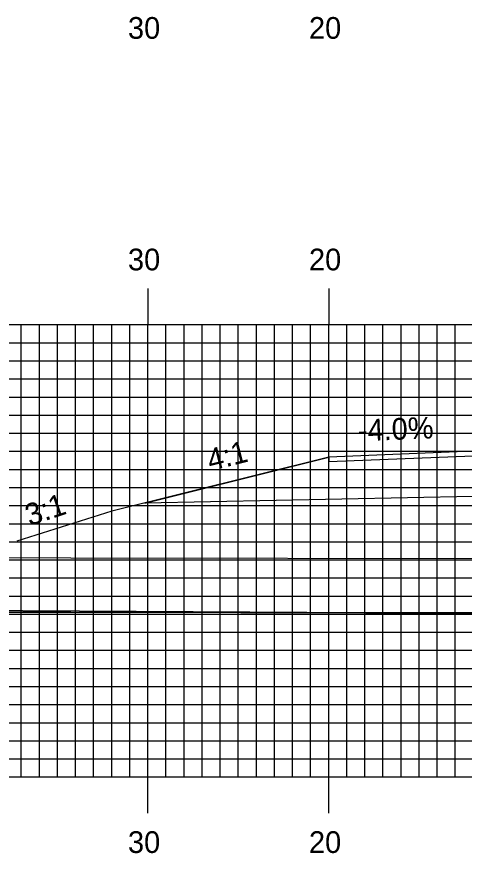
# Model space of a CAD drawing. Extents: x 1804290 to 1804634, y 442591 to 442811.
# Drawn here: x 1804418.91 to 1804443.67, y 442649.45 to 442695.68 of the extents above; entities that cross this region are included whole.
import ezdxf

# ---------------------------------------------------------------- set-up
doc = ezdxf.new("R2010")
doc.units = 0
for name, color, linetype in [('ANNOTATION', 7, 'Continuous'), ('D_Drainage_Culvert', 7, 'Continuous'), ('D_Roadway_Edge_Shoulder', 7, 'Continuous'), ('D_Roadway_SlopeLines', 7, 'Continuous'), ('D_Roadway_SubGrade', 7, 'Continuous'), ('H_V ANNOTATION', 7, 'Continuous'), ('MAJOR', 7, 'Continuous'), ('MINOR', 7, 'Continuous'), ('S_Roadway_Centerline', 7, 'Continuous')]:
    doc.layers.add(name, color=color, linetype=linetype)

msp = doc.modelspace()

# ---------------------------------------------------------------- linework, layer by layer
at = {"layer": 'D_Drainage_Culvert'}
msp.add_line((1804407.504, 442662.794), (1804505.89, 442662.656), dxfattribs=at)
msp.add_lwpolyline([(1804409.888, 442662.791), (1804409.893, 442665.791), (1804505.893, 442665.645), (1804505.888, 442662.645)], close=True, dxfattribs=at)
at = {"layer": 'D_Roadway_Edge_Shoulder'}
msp.add_lwpolyline([(1804444.167, 442671.668), (1804436.167, 442671.348), (1804436.167, 442671.098), (1804444.167, 442671.418)], close=True, dxfattribs=at)
at = {"layer": 'D_Roadway_SlopeLines'}
msp.add_lwpolyline([(1804436.167, 442671.348), (1804424.167, 442668.348), (1804418.912, 442666.699)], dxfattribs=at)
at = {"layer": 'D_Roadway_SubGrade'}
msp.add_lwpolyline([(1804444.167, 442669.168), (1804425.993, 442668.805), (1804436.167, 442671.348), (1804436.167, 442671.098), (1804444.167, 442671.418), (1804456.167, 442671.706), (1804468.167, 442671.994), (1804476.167, 442671.674), (1804476.167, 442671.924), (1804486.341, 442669.381), (1804468.167, 442669.744), (1804456.167, 442669.456)], close=True, dxfattribs=at)
at = {"layer": 'MAJOR'}
for p, q in [((1804426.167, 442680.669), (1804426.167, 442678.665)), ((1804436.167, 442680.669), (1804436.167, 442678.665)), ((1804316.167, 442678.665), (1804596.167, 442678.665)), ((1804316.167, 442678.665), (1804596.167, 442678.665)), ((1804426.167, 442653.665), (1804426.167, 442678.665)), ((1804436.167, 442653.665), (1804436.167, 442678.665)), ((1804316.167, 442673.665), (1804596.167, 442673.665)), ((1804316.167, 442668.665), (1804596.167, 442668.665)), ((1804316.167, 442663.665), (1804596.167, 442663.665)), ((1804316.167, 442658.665), (1804596.167, 442658.665)), ((1804316.167, 442653.665), (1804596.167, 442653.665)), ((1804316.167, 442653.665), (1804596.167, 442653.665)), ((1804426.167, 442651.661), (1804426.167, 442653.665)), ((1804436.167, 442651.661), (1804436.167, 442653.665))]:
    msp.add_line(p, q, dxfattribs=at)
at = {"layer": 'MINOR'}
for p, q in [((1804419.167, 442653.665), (1804419.167, 442678.665)), ((1804420.167, 442653.665), (1804420.167, 442678.665)), ((1804421.167, 442653.665), (1804421.167, 442678.665)), ((1804422.167, 442653.665), (1804422.167, 442678.665)), ((1804423.167, 442653.665), (1804423.167, 442678.665)), ((1804424.167, 442653.665), (1804424.167, 442678.665)), ((1804425.167, 442653.665), (1804425.167, 442678.665)), ((1804427.167, 442653.665), (1804427.167, 442678.665)), ((1804428.167, 442653.665), (1804428.167, 442678.665)), ((1804429.167, 442653.665), (1804429.167, 442678.665)), ((1804430.167, 442653.665), (1804430.167, 442678.665)), ((1804431.167, 442653.665), (1804431.167, 442678.665)), ((1804432.167, 442653.665), (1804432.167, 442678.665)), ((1804433.167, 442653.665), (1804433.167, 442678.665)), ((1804434.167, 442653.665), (1804434.167, 442678.665)), ((1804435.167, 442653.665), (1804435.167, 442678.665)), ((1804437.167, 442653.665), (1804437.167, 442678.665)), ((1804438.167, 442653.665), (1804438.167, 442678.665)), ((1804439.167, 442653.665), (1804439.167, 442678.665)), ((1804440.167, 442653.665), (1804440.167, 442678.665)), ((1804441.167, 442653.665), (1804441.167, 442678.665)), ((1804442.167, 442653.665), (1804442.167, 442678.665)), ((1804443.167, 442653.665), (1804443.167, 442678.665)), ((1804316.167, 442677.665), (1804596.167, 442677.665)), ((1804316.167, 442676.665), (1804596.167, 442676.665)), ((1804316.167, 442675.665), (1804596.167, 442675.665)), ((1804316.167, 442674.665), (1804596.167, 442674.665)), ((1804316.167, 442672.665), (1804596.167, 442672.665)), ((1804316.167, 442671.665), (1804596.167, 442671.665)), ((1804316.167, 442670.665), (1804596.167, 442670.665)), ((1804316.167, 442669.665), (1804596.167, 442669.665)), ((1804316.167, 442667.665), (1804596.167, 442667.665)), ((1804316.167, 442666.665), (1804596.167, 442666.665)), ((1804316.167, 442665.665), (1804596.167, 442665.665)), ((1804316.167, 442664.665), (1804596.167, 442664.665)), ((1804316.167, 442662.665), (1804596.167, 442662.665)), ((1804316.167, 442661.665), (1804596.167, 442661.665)), ((1804316.167, 442660.665), (1804596.167, 442660.665)), ((1804316.167, 442659.665), (1804596.167, 442659.665)), ((1804316.167, 442657.665), (1804596.167, 442657.665)), ((1804316.167, 442656.665), (1804596.167, 442656.665)), ((1804316.167, 442655.665), (1804596.167, 442655.665)), ((1804316.167, 442654.665), (1804596.167, 442654.665))]:
    msp.add_line(p, q, dxfattribs=at)
at = {"layer": 'S_Roadway_Centerline'}
msp.add_lwpolyline([(1804392.455, 442662.786), (1804403.753, 442662.746), (1804414.339, 442662.882), (1804416.075, 442662.891), (1804434.951, 442662.77), (1804441.486, 442662.699), (1804450.248, 442662.785), (1804459.333, 442662.638), (1804461.991, 442662.67), (1804464.615, 442662.608), (1804482.103, 442662.436), (1804485.564, 442662.421), (1804488.839, 442662.416), (1804494.685, 442662.541), (1804511.409, 442662.696), (1804519.927, 442662.797)], dxfattribs=at)

# ---------------------------------------------------------------- texts
at = {"layer": 'ANNOTATION'}
for s, rotation, p in [('-4.0%', 2.2906, (1804437.799, 442672.215)), ('4:1', 14.0362, (1804429.616, 442670.572)), ('3:1', 18.4348, (1804419.624, 442667.523))]:
    msp.add_text(s, height=1.2, rotation=rotation, dxfattribs=at).set_placement(p)
at = {"layer": 'H_V ANNOTATION'}
for s, p in [('30', (1804425.064, 442694.465)), ('20', (1804435.075, 442694.465)), ('30', (1804425.064, 442681.665)), ('20', (1804435.075, 442681.665)), ('30', (1804425.064, 442649.465)), ('20', (1804435.075, 442649.465))]:
    msp.add_text(s, height=1.2, dxfattribs=at).set_placement(p)

doc.saveas('drawing.dxf')
